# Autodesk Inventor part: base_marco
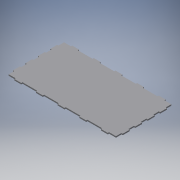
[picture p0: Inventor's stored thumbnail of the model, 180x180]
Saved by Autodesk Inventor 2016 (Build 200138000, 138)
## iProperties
Created: 2017-06
Part Number: base_marco
Material: Generic
Document SubType Name: Modeling
Designer: laboratorioesan
Density: 1 g/cm^3
Appearance: Default
Author: laboratorioesan
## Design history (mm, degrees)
sketch "Sketch1"
  geometry: L1 (312.5, 0)-(412.5, 0) reference; L2 (312.5, 0)-(312.5, -18.5) reference; L3 (412.5, -18.5)-(312.5, -18.5) reference; L4 (412.5, 0)-(412.5, -18.5) reference; L5 (0, 0)-(100, 0) reference; L6 (0, 0)-(0, -18.5) reference; L7 (100, -18.5)-(0, -18.5) reference; L8 (100, 0)-(100, -18.5) reference; L9 (512.5, 80)-(512.5, 180) reference; L10 (512.5, 80)-(531, 80) reference; L11 (531, 180)-(531, 80) reference; L12 (512.5, 180)-(531, 180) reference; L13 (512.5, 620)-(512.5, 720) reference; L14 (512.5, 620)-(531, 620) reference; L15 (531, 720)-(531, 620) reference; L16 (512.5, 720)-(531, 720) reference; L17 (512.5, 440)-(512.5, 540) reference; L18 (512.5, 440)-(531, 440) reference; L19 (531, 540)-(531, 440) reference; L20 (512.5, 540)-(531, 540) reference; L21 (512.5, 260)-(512.5, 360) reference; L22 (512.5, 260)-(531, 260) reference; L23 (531, 360)-(531, 260) reference; L24 (512.5, 360)-(531, 360) reference; L25 (312.5, 818.5)-(412.5, 818.5) reference; L26 (312.5, 818.5)-(312.5, 800) reference; L27 (412.5, 800)-(312.5, 800) reference; L28 (412.5, 818.5)-(412.5, 800) reference; L29 (0, 818.5)-(100, 818.5) reference; L30 (0, 818.5)-(0, 800) reference; L31 (100, 800)-(0, 800) reference; L32 (100, 818.5)-(100, 800) reference; L33 (-312.5, 818.5)-(-212.5, 818.5) reference; L34 (-312.5, 818.5)-(-312.5, 800) reference; L35 (-212.5, 800)-(-312.5, 800) reference; L36 (-212.5, 818.5)-(-212.5, 800) reference; L37 (-625, 818.5)-(-525, 818.5) reference; L38 (-625, 818.5)-(-625, 800) reference; L39 (-525, 800)-(-625, 800) reference; L40 (-525, 818.5)-(-525, 800) reference; L41 (-937.5, 818.5)-(-837.5, 818.5) reference; L42 (-937.5, 818.5)-(-937.5, 800) reference; L43 (-837.5, 800)-(-937.5, 800) reference; L44 (-837.5, 818.5)-(-837.5, 800) reference; L45 (-1037.5, 720)-(-1037.5, 620) reference; L46 (-1037.5, 720)-(-1056, 720) reference; L47 (-1056, 620)-(-1056, 720) reference; L48 (-1037.5, 620)-(-1056, 620) reference; L49 (-1037.5, 540)-(-1037.5, 440) reference; L50 (-1037.5, 540)-(-1056, 540) reference; L51 (-1056, 440)-(-1056, 540) reference; L52 (-1037.5, 440)-(-1056, 440) reference; L53 (-1037.5, 360)-(-1037.5, 260) reference; L54 (-1037.5, 360)-(-1056, 360) reference; L55 (-1056, 260)-(-1056, 360) reference; L56 (-1037.5, 260)-(-1056, 260) reference; L57 (-1037.5, 180)-(-1037.5, 80) reference; L58 (-1037.5, 180)-(-1056, 180) reference; L59 (-1056, 80)-(-1056, 180) reference; L60 (-1037.5, 80)-(-1056, 80) reference; L61 (-937.5, 0)-(-837.5, 0) reference; L62 (-937.5, 0)-(-937.5, -18.5) reference; L63 (-837.5, -18.5)-(-937.5, -18.5) reference; L64 (-837.5, 0)-(-837.5, -18.5) reference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
  constraints: 152 end point, 38 parallel, 19 horizontal, 19 perpendicular, 18 point on line
  dimensions: "d0" = 18 distance of L82.end L81.end; "d1" = 18 distance of L86.end L85.end; "d2" = 18 distance of L90.end L89.end; "d3" = 18 distance of L94.end L93.end; "d4" = 18 distance of L98.end L97.end; "d5" = 18 distance of L102.end L103.end; "d6" = 18 distance of L106.end L107.end; "d7" = 18 distance of L110.end L111.end; "d8" = 18 distance of L114.end L115.end; "d9" = 18 distance of L118.end L117.end; "d10" = 18 distance of L122.end L121.end; "d11" = 18 distance of L126.end L125.end; "d12" = 18 distance of L129.end L130.end; "d13" = 18 distance of L134.end L133.end; "d14" = 18 distance of L138.end L139.end; "d15" = 18 distance of L142.end L143.end; "d16" = 18 distance of L146.end L147.end; "d17" = 18 distance of L150.end L151.end
extrude "Extrusion1" new body sketch "Sketch1" distance "d18" = 15.5; taper "d19" = 0 deg
body "Solid1"
node "Reference1"
node "Reference2"
node "Reference3"
node "Reference4"
node "Reference5"
node "Reference6"
node "Reference7"
node "Reference8"
node "Reference9"
node "Reference10"
node "Reference11"
node "Reference12"
node "Reference13"
node "Reference14"
node "Reference15"
node "Reference16"
node "Reference17"
node "Reference18"
node "Reference19"
node "Reference20"
node "Reference21"
node "Reference22"
